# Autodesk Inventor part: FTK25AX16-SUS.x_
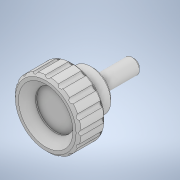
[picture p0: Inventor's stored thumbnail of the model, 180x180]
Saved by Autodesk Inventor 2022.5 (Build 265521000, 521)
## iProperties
Created: 2023-10
Part Number: FTK25AX16-SUS.x_
Material: 一般
Document SubType Name: Modeling
Designer: ImaoCorp
Density: 1 g/cm^3
Appearance: 既定
Sending System: SOLIDWORKS 2021-2021301
MC: AMD64
MC_MODEL: Intel64 Family 6 Model 60 Stepping 3, GenuineIntel
OS: Windows_NT
FRU: Parasolid Version 32.1, build 255,  1- 1-2021
FORMAT: text
GUISE: transmit
KEY: FTK25AX16-SUS
FILE: FTK25AX16-SUS.x_t
DATE: Tue Oct 17 11:07:37 2023
Author: ImaoCorp
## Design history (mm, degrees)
feature "Base1"
node "ソリッド1"
